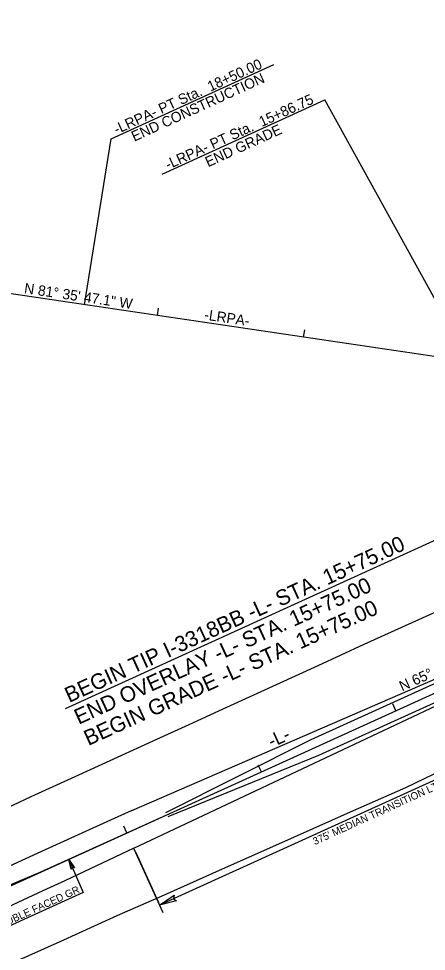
# Model space of a CAD drawing. Extents: x 2242984 to 2250974, y 661492 to 664681.
# Drawn here: x 2247792 to 2248068, y 662790 to 663422 of the extents above; entities that cross this region are included whole.
import ezdxf

# ---------------------------------------------------------------- set-up
doc = ezdxf.new("R2010")
doc.units = 0
for name, color, linetype in [('Prop Dimension', 7, 'Continuous'), ('Prop Dimension Text', 7, 'Continuous'), ('Prop DSN Text', 7, 'Continuous'), ('Prop Guardrail', 7, 'Continuous'), ('Prop Guardrail Double Faced', 7, 'Continuous'), ('Prop Horizontal Alignment', 7, 'Continuous'), ('Prop Horizontal Alignment Curve and Spiral Data', 7, 'Continuous'), ('Prop Horizontal Alignment Direction Label', 7, 'Continuous'), ('Prop Horizontal Alignment Station Label', 7, 'Continuous'), ('Prop Horizontal Alignment Tick Small', 7, 'Continuous'), ('Prop Paved Shoulder', 7, 'Continuous'), ('Prop Terminator CELL', 7, 'Continuous'), ('Scratch_Level_2', 7, 'Continuous'), ('Typical Terminator CELL', 7, 'Continuous')]:
    doc.layers.add(name, color=color, linetype=linetype)

# ---------------------------------------------------------------- blocks, each defined once
blk = doc.blocks.new('TERMINATOR')
at = {"layer": 'Typical Terminator CELL'}
blk.add_lwpolyline([(-0.469, 0.081), (0, 0), (-0.471, -0.083), (-0.411, 0)], close=True, dxfattribs=at)

msp = doc.modelspace()

# ---------------------------------------------------------------- linework, layer by layer
at = {"layer": 'Prop Dimension'}
for p, q in [((2247823.34, 662954.6), (2248075.06, 663069.31)), ((2248228.6, 662976.68), (2247887.17, 662821.59)), ((2247889.59, 662816.28), (2247869.96, 662859.5)), ((2247870.99, 662857.23), (2247886.41, 662823.28))]:
    msp.add_line(p, q, dxfattribs=at)
at = {"layer": 'Prop DSN Text'}
for p, q in [((2247825.63, 662852.58), (2247835.37, 662830.21)), ((2247835.37, 662830.21), (2247774.77, 662802.6))]:
    msp.add_line(p, q, dxfattribs=at)
at = {"layer": 'Prop Guardrail'}
for p, q in [((2248855.32, 663313.72), (2247994.71, 662922.79)), ((2248855.32, 663313.72), (2247994.71, 662922.79)), ((2247989.75, 662933.71), (2248810.53, 663306.55)), ((2247989.75, 662933.71), (2248810.53, 663306.55)), ((2247891.41, 662884.21), (2247989.75, 662933.71)), ((2247994.71, 662922.79), (2247892.73, 662881.3))]:
    msp.add_line(p, q, dxfattribs=at)
at = {"layer": 'Prop Guardrail Double Faced'}
for p, q in [((2247806.38, 662843.83), (2247892.07, 662882.75)), ((2247701.8, 662800.52), (2247806.38, 662843.83))]:
    msp.add_line(p, q, dxfattribs=at)
at = {"layer": 'Prop Horizontal Alignment'}
for p, q in [((2247500.8, 662705.02), (2249793.08, 663746.29)), ((2248096.71, 663189.45), (2247556.64, 663269.24))]:
    msp.add_line(p, q, dxfattribs=at)
at = {"layer": 'Prop Horizontal Alignment Station Label'}
for p, q in [((2247854.28, 663340.3), (2247964.48, 663390.51)), ((2247888.87, 663316.31), (2247999.07, 663366.52)), ((2248095.99, 663190.77), (2247999.07, 663366.52)), ((2247836.29, 663227.93), (2247854.28, 663340.3))]:
    msp.add_line(p, q, dxfattribs=at)
at = {"layer": 'Prop Horizontal Alignment Tick Small'}
for p, q in [((2247885.76, 663220.62), (2247886.49, 663225.56)), ((2247984.68, 663206), (2247985.41, 663210.95)), ((2248047.08, 662953.17), (2248045.01, 662957.72)), ((2247956.03, 662911.81), (2247953.96, 662916.36)), ((2247864.98, 662870.45), (2247862.92, 662875))]:
    msp.add_line(p, q, dxfattribs=at)
at = {"layer": 'Prop Paved Shoulder'}
for p, q in [((2247868.29, 662885.73), (2248203.91, 663031)), ((2247869.62, 662860.25), (2248208.86, 663020.07))]:
    msp.add_line(p, q, dxfattribs=at)
for points in [[(2247708.16, 662853), (2247737.81, 662866.51), (2247762.85, 662877.4), (2247800.12, 662895.08), (2247832.44, 662909.7), (2247861.63, 662923.16), (2247885.32, 662933.83), (2247909.61, 662945.06), (2247924.85, 662952.02), (2247966.34, 662970.9), (2247994.49, 662983.87), (2248025.59, 662998.19), (2248058.08, 663012.97), (2248088.08, 663026.44), (2248119.82, 663041.08), (2248150.21, 663054.44), (2248181.1, 663069.6), (2248182.96, 663070.48)], [(2247748.12, 662765.04), (2247749.91, 662765.84), (2247788.02, 662782.85), (2247819.89, 662797), (2247858.38, 662814.46), (2247890.52, 662828.54), (2247929.75, 662846.07), (2247965.79, 662862.18), (2248016.34, 662884.69), (2248053.87, 662901.09), (2248085.69, 662916.48), (2248123.17, 662934.34), (2248153.89, 662949.09), (2248186.42, 662964.72), (2248216.92, 662976.74)], [(2247868.29, 662885.73), (2247836.92, 662871.41), (2247807.27, 662857.99), (2247776.94, 662844.21), (2247750.19, 662832.27), (2247729.91, 662823.2), (2247723.1, 662820.1)], [(2247869.62, 662860.25), (2247822.9, 662837.97), (2247808.1, 662831.33), (2247770.17, 662813.66), (2247733.51, 662797.2)]]:
    msp.add_lwpolyline(points, dxfattribs=at)
at = {"layer": 'Prop Terminator CELL'}
msp.add_lwpolyline([(2247827.26, 662845.93), (2247825.63, 662852.58), (2247829.44, 662846.84), (2247827.99, 662847.15)], close=True, dxfattribs=at)
at = {"layer": 'Scratch_Level_2'}
for points in [[(2247708.16, 662853), (2247737.81, 662866.51), (2247762.85, 662877.4), (2247800.12, 662895.08), (2247832.44, 662909.7), (2247861.63, 662923.16), (2247885.32, 662933.83), (2247909.61, 662945.06), (2247924.85, 662952.02), (2247966.34, 662970.9), (2247994.49, 662983.87), (2248025.59, 662998.19), (2248058.08, 663012.97), (2248088.08, 663026.44), (2248119.82, 663041.08), (2248150.21, 663054.44), (2248181.1, 663069.6), (2248182.96, 663070.48)], [(2247748.12, 662765.04), (2247749.91, 662765.84), (2247788.02, 662782.85), (2247819.89, 662797), (2247858.38, 662814.46), (2247890.52, 662828.54), (2247929.75, 662846.07), (2247965.79, 662862.18), (2248016.34, 662884.69), (2248053.87, 662901.09), (2248085.69, 662916.48), (2248123.17, 662934.34), (2248153.89, 662949.09), (2248186.42, 662964.72), (2248216.92, 662976.74)]]:
    msp.add_lwpolyline(points, dxfattribs=at)

# ---------------------------------------------------------------- block references
at = {"layer": 'Prop Dimension', "xscale": 24.999999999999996, "yscale": 25, "rotation": -155.56987410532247}
msp.add_blockref('TERMINATOR', (2247887.17, 662821.59), dxfattribs=at)

# ---------------------------------------------------------------- texts
at = {"layer": 'Prop Dimension'}
for s, p in [('BEGIN TIP I-3318BB -L- STA. 15+75.00  ', (2247825.93, 662958.35)), ('END OVERLAY -L- STA. 15+75.00', (2247832.37, 662943.57)), ('BEGIN GRADE -L- STA. 15+75.00', (2247838.9, 662929.24))]:
    msp.add_text(s, height=10.5, rotation=24.49794, dxfattribs=at).set_placement(p)
at = {"layer": 'Prop Dimension Text'}
msp.add_text("375' MEDIAN TRANSITION LT & RT", height=5, rotation=24.49794, dxfattribs=at).set_placement((2247992.24, 662862.13))
at = {"layer": 'Prop DSN Text'}
msp.add_text('DOUBLE FACED GR', height=5, rotation=24.49794, dxfattribs=at).set_placement((2247775.37, 662803.85))
at = {"layer": 'Prop Horizontal Alignment Curve and Spiral Data'}
for s, height, rotation, p in [('-LRPA-', 7, 351.59641, (2247917.1, 663217.91)), ('-L-', 9, 24.43013, (2247963, 662927.97))]:
    msp.add_text(s, height=height, rotation=rotation, dxfattribs=at).set_placement(p)
at = {"layer": 'Prop Horizontal Alignment Direction Label'}
for s, rotation, p in [('N 81%%d 35\' 47.1" W', 351.59641, (2247795.14, 663235.79)), ('N 65%%d 34\' 11.5" E', 24.43013, (2248051.36, 662966.16))]:
    msp.add_text(s, height=7, rotation=rotation, dxfattribs=at).set_placement(p)
at = {"layer": 'Prop Horizontal Alignment Station Label'}
for s, p in [('-LRPA- PT Sta.  18+50.00', (2247858.07, 663343.12)), ('END CONSTRUCTION', (2247870.02, 663338.22)), ('-LRPA- PT Sta.  15+86.75', (2247892.92, 663319.25)), ('END GRADE', (2247919.98, 663320.93))]:
    msp.add_text(s, height=7, rotation=24.49794, dxfattribs=at).set_placement(p)

doc.saveas('drawing.dxf')
